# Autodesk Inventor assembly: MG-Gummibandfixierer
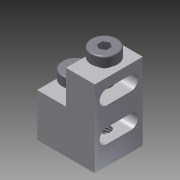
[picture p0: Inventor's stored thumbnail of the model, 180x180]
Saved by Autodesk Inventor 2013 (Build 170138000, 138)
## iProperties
Created: 2012-08
Part Number: MG-Gummibandfixierer
Document SubType Name: Assembly
Designer: rYan
Mass: 4.0488 g
Surface Area: 14.5331 cm^2
Volume: 1.20502 cm^3
Density: 3.35996 g/cm^3
Author: rYan
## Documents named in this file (3)
- C:\Users\SteffenHaase\Desktop\Tigers\2013\Inventor\Kicker\MG-Gummibandfixierer.iam
- C:\Users\SteffenHaase\Desktop\Tigers\2013\Inventor\Kicker\Gummibandfixierer.ipt
- C:\Users\SteffenHaase\Desktop\Tigers\2013\Inventor\Inhaltscenter\de-DE\DIN 7984\DIN 7984 - M3 x 5.ipt
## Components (3 placed, 2 different names)
1. Gummibandfixierer:1 — Passend:3, Passend:5
2. DIN 7984 M3 x 5:1 — Passend:3
3. DIN 7984 M3 x 5:2 — Passend:5
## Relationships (2: Mate 2)
- Passend:3 [Mate]: Gummibandfixierer:1 ↔ DIN 7984 M3 x 5:1
- Passend:5 [Mate]: Gummibandfixierer:1 ↔ DIN 7984 M3 x 5:2
